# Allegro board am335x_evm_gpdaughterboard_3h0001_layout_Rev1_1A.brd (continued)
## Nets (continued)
VDDSHV1: C1.1 C21.1 C22.1 C23.1 C24.1 C25.1 C30.1 C31.1 C35.1 C36.1 C37.1 C38.1 C80.1 C81.1 R1.2(P2) R2.2(P2) R6.2(P2) R18.2(P2) R19.2(P2) R20.2(P2) R247.2(P2) U1.1(A0) U1.8(VCC) U5.12(VCC#12) U5.34(VCC#34) U5.37(VCC#37) U5.39(VCC#39) U6.31(VCCA#31) U6.42(VCCA#42) U7.7(VCCB#7) U7.18(VCCB#18) U7.31(VCCA#31) U7.42(VCCA#42) U23.5(VCCA) U23.17(VCCB1)
VDDSHV2: C7.1 C77.1 J4.11 R47.2(P2) U23.21(VCCB0)
VDDSHV3: C26.1 C28.1 R3.2(P2) R7.2(P2) U4.1(1DIR) U4.24(2DIR) U4.31(VCCA#31) U4.42(VCCA#42)
VDDSHV5: R4.2(P2) R8.2(P2)
VDDSHV6: C13.1 C14.1 C40.1 C44.1 R5.2(P2) R9.2(P2) U2.1(1DIR) U2.24(2DIR) U2.31(VCCA#31) U2.42(VCCA#42) U10.3(VCCA) U11.3(VCCA)
ACCEL_INT1: U9.11(INT1) U43.L5(IO_B1_L5)
ACCEL_INT2: U9.9(INT2) U43.L6(IO_B1_L6)
AM335X_ECAP0_IN_PWM0_OUT: J3.19 U43.B12(IO_B2_B12)
AM335X_GPMC_A0: J4.2 U43.D9(IO_B2_D9)
AM335X_GPMC_A1: J4.4 U43.D10(IO_B2_D10)
AM335X_GPMC_A2: J4.6 U43.D11(IO_B2_D11)
AM335X_GPMC_A3: J4.8 U43.D12(IO_B2_D12)
AM335X_GPMC_A4: J4.10 U4.41(1A5) U43.D13(IO_B2_D13)
AM335X_GPMC_A5: J4.12 U4.40(1A6) U43.D14(IO_B2_D14)
AM335X_GPMC_A6: J4.16 U4.38(1A7) U43.E6(IO_B2_E6)
AM335X_GPMC_A7: J4.18 U4.37(1A8) U43.E7(IO_B2_E7)
AM335X_GPMC_A8: J4.22 U4.47(1A1) U43.E8(IO_B2_E8)
AM335X_GPMC_A9: J4.24 U4.46(1A2) U43.E9(IO_B2_E9)
AM335X_GPMC_A10: J4.26 U4.44(1A3) U43.E10(IO_B2_E10)
AM335X_GPMC_A11: J4.28 U4.43(1A4) U43.E11(IO_B2_E11)
AM335X_GPMC_AD0: J1.17 U23.6(DAT0A)
AM335X_GPMC_AD1: J1.15 U23.7(DAT1A)
AM335X_GPMC_AD2: J1.13 U23.1(DAT2A)
AM335X_GPMC_AD3: J1.11 U23.3(DAT3A)
AM335X_GPMC_AD4: J1.9 R251.2(P2) R255.2(P2)
AM335X_GPMC_AD5: J1.7 R252.2(P2) R257.2(P2)
AM335X_GPMC_AD6: J1.5 R253.2(P2) R256.2(P2)
AM335X_GPMC_AD7: J1.3 R254.2(P2) R258.2(P2)
AM335X_GPMC_AD8: J5.11 U43.R14(IO_B4_R14)
AM335X_GPMC_AD9: J5.14 U43.R13(IO_B4_R13)
AM335X_GPMC_AD10: J6.4 U43.R12(IO_B4_R12)
AM335X_GPMC_AD11: J6.3 U43.R11(IO_B4_R11)
AM335X_GPMC_AD12: J5.13 U43.R10(IO_B4_R10)
AM335X_GPMC_AD13: J6.6 U43.P13(IO_B4_P13)
AM335X_GPMC_AD14: J6.5 U43.P12(IO_B4_P12)
AM335X_GPMC_AD15: J6.8 U43.P11(IO_B4_P11)
AM335X_GPMC_ADVN_ALE: J2.26 U43.G7(IO_B1_G7)
AM335X_GPMC_BE0N_CLE: J2.28 U43.H1(IO_B1_H1)
AM335X_GPMC_BE1N: J3.2 U43.J1(IO_B1_J1)
AM335X_GPMC_CLK: J2.23 U43.H4(IO_B1_H4)
AM335X_GPMC_CS0N: J2.25 U43.H5(IO_B1_H5)
AM335X_GPMC_CS1N: J1.21 U23.9(CLKA)
AM335X_GPMC_CS2N: J1.19 U23.4(CMDA)
AM335X_GPMC_CS3N: J3.4 U43.J2(IO_B1_J2)
AM335X_GPMC_OEN_REN: J3.6 U43.J3(IO_B1_J3)
AM335X_GPMC_WAIT: J2.19 U43.H2(IO_B1_H2)
AM335X_GPMC_WEN: J3.8 U43.A2(IO_B2_A2)
AM335X_GPMC_WPN: J2.21 U43.H3(IO_B1_H3)
AM335X_I2C0_SCL: J6.14 J20.14 U1.6(SCL) U43.M5(IO_B1_M5)
AM335X_I2C0_SDA: J5.15 J19.15 U1.5(SDA) U43.M6(IO_B1_M6)
AM335X_MCASP0_ACLKR: J4.17 U43.F9(IO_B2_F9)
AM335X_MCASP0_ACLKX: J4.1 U43.E12(IO_B2_E12)
AM335X_MCASP0_AHCLKR: J4.13 U43.F8(IO_B2_F8)
AM335X_MCASP0_AHCLKX: J4.27 U43.F12(IO_B2_F12)
AM335X_MCASP0_AXR0: J4.7 U43.F7(IO_B2_F7)
AM335X_MCASP0_AXR1: J4.23 U43.F11(IO_B2_F11)
AM335X_MCASP0_FSR: J4.21 U43.F10(IO_B2_F10)
AM335X_MCASP0_FSX: J4.5 U43.E13(IO_B2_E13)
AM335X_MDIO_CLK: J3.9 TP79.1
AM335X_MDIO_DATA: J3.7 TP78.1
AM335X_MMC0_CLK: J3.12 U43.A4(IO_B2_A4)
AM335X_MMC0_CMD: J3.14 U43.A5(IO_B2_A5)
AM335X_MMC0_DAT0: J3.16 U43.A6(IO_B2_A6)
AM335X_MMC0_DAT1: J3.22 U43.A8(IO_B2_A8)
AM335X_MMC0_DAT2: J3.24 U43.A9(IO_B2_A9)
AM335X_MMC0_DAT3: J3.26 U43.A10(IO_B2_A10)
AM335X_RMII1_COL: J3.34 U43.A17(IO_B2_A17)
AM335X_RMII1_CRS: J3.36 U43.B1(IO_B2_B1)
AM335X_RMII1_REFCLK: J3.3 U43.B5(IO_B2_B5)
AM335X_RMII1_RXCLK: J1.8 U43.D1(IO_B1_D1)
AM335X_RMII1_RXD0: J3.5 U43.B6(IO_B2_B6)
AM335X_RMII1_RXD1: J1.22 U43.E4(IO_B1_E4)
AM335X_RMII1_RXD2: J1.10 U43.D2(IO_B1_D2)
AM335X_RMII1_RXD3: J1.4 U43.C2(IO_B1_C2)
AM335X_RMII1_RXDV: J1.14 U43.D4(IO_B1_D4)
AM335X_RMII1_RXERR: J3.38 U43.B3(IO_B2_B3)
AM335X_RMII1_TXCLK: J1.6 U43.C3(IO_B1_C3)
AM335X_RMII1_TXD0: J1.20 U43.E3(IO_B1_E3)
AM335X_RMII1_TXD1: J1.18 U43.E2(IO_B1_E2)
AM335X_RMII1_TXD2: J1.12 U43.D3(IO_B1_D3)
AM335X_RMII1_TXD3: J1.16 U43.E1(IO_B1_E1)
AM335X_RMII1_TXEN: J3.40 U43.B4(IO_B2_B4)
AM335X_SPI0_CLK: J3.13 U43.B9(IO_B2_B9)
AM335X_SPI0_CS0: J1.24 U10.5(A1) U43.E5(IO_B1_E5)
AM335X_SPI0_CS1: J3.17 U43.B11(IO_B2_B11)
AM335X_SPI0_D0: J3.15 U43.B10(IO_B2_B10)
AM335X_SPI0_D1: J1.23 U10.4(A2) U43.G6(IO_B1_G6)
AM335X_TSC_CLK: J7.5 U43.T7(IO_B4_T7)
AM335X_TSC_GIO0: J7.1 U43.T5(IO_B4_T5)
AM335X_TSC_GIO1: J7.3 U43.T6(IO_B4_T6)
AM335X_TSC_GIO2: J7.8 U43.T10(IO_B4_T10)
AM335X_TSC_RSV0: J7.7 TP4.1
AM335X_TSC_RSV1_VREF: J7.9 TP5.1
AM335X_UART0_CTSN: J3.21 U43.B13(IO_B2_B13)
AM335X_UART0_RTSN: J3.23 U43.B14(IO_B2_B14)
AM335X_UART0_RXD: J3.25 U43.B15(IO_B2_B15)
AM335X_UART0_TXD: J3.27 U43.B16(IO_B2_B16)
AM335X_UART1_CTSN: J3.29 U11.4(A2) U43.B18(IO_B2_B18)
AM335X_UART1_RTSN: J3.31 U11.5(A1) U43.C4(IO_B2_C4)
AM335X_UART1_RXD: J3.33 U43.C5(IO_B2_C5)
AM335X_UART1_TXD: J3.35 U43.C6(IO_B2_C6)
AM335X_WAKEUP: J3.18 R126.1(P1) U42.6(1Y) U43.A7(IO_B2_A7)
AM335X_XDMA_EVENT_INTR0: J3.28 U43.A14(IO_B2_A14)
AM335X_XDMA_EVENT_INTR1: J3.32 R158.2(P2) U43.A15(IO_B2_A15)
AUD_BCLK: U43.E15(IO_B3_E15) U51.38(BCLK)
AUD_DIN: U43.F15(IO_B3_F15) U51.40(DIN)
AUD_DOUT: U43.F14(IO_B3_F14) U51.41(DOUT)
AUD_FSX: U43.F13(IO_B3_F13) U51.39(WCLK)
AUD_HPLOUT: C198.1 U51.18(HPLOUT)
AUD_HPLOUT_JCK: C198.2 J26.2(P2)
AUD_HPOUTCABLEDET: U43.K14(IO_B3_K14)
AUD_HPROUT: C197.1 U51.23(HPROUT)
AUD_HPROUT_JCK: C197.2 J26.3(P3)
AUD_LINEINCABLEDET: U43.K15(IO_B3_K15)
AUD_MCLK: R231.1(P1) R233.1(P1) U51.37(MCLK)
AUD_MCLK_CPLD: R233.2(P2) U43.E16(IO_B3_E16)
AUD_RESETN: R232.1(P1) U51.33(RESETN)
AUD_VOLUMEDWN: R236.1(P1) SW10.1 SW10.2 U43.R6(IO_B4_R6)
AUD_VOLUMEUP: R235.1(P1) SW9.1 SW9.2 U43.R5(IO_B4_R5)
AUDIO_BUZZER_TRIG: Q9.G(GATE) R124.2(P2) U43.L4(IO_B1_L4)
BUZZER_N: Q9.D(DRAIN) SPKR1.2(NEG-)
BUZZER_P: R120.1 SPKR1.1(POS+)
CAN0_H: J11.7 U16.7(CANH) U17.1
CAN0_L: J11.2 U16.6(CANL) U17.2
CAN0_RXD: C57.1 R43.1 U43.J15(IO_B3_J15)
CAN0_RXDF: R43.2 U16.2(RXD)
CAN0_TXD: R44.1 U43.J16(IO_B3_J16)
CAN0_TXDF: C58.1 R44.2 U16.3(TXD)
CPLD_CFG0: R151.2(P2) SW8.1 U43.P10(IO_B4_P10)
CPLD_CFG1: R150.2(P2) SW8.2 U43.R7(IO_B4_R7)
CPLD_CFG2: R149.2(P2) SW8.3 U43.R8(IO_B4_R8)
CPLD_CFG3: R148.2(P2) SW8.4 U43.R9(IO_B4_R9)
CPLD_CLK12MHZ: R230.1(P1) U43.J6(GCLK0P)
CPLD_CLK25MHZ: R157.1(P1) U43.K6(GCLK1P)
CPLD_CLKSA: R158.1(P1) U43.K13(GCLK2P)
CPLD_CLRN: R156.1(P1) U43.N10(DEV_CLRN)
CPLD_DEVOE: TP32.1 U43.N9(DEV_OE)
CPLD_GCLK3: TP33.1 U43.J13(GCLK3P)
CPLD_TCK: J22.1 R159.2(P2) U43.R4(TCK)
CPLD_TDI: J22.9 R153.1(P1) U43.M7(TDI)
CPLD_TDO: J22.3 R154.1(P1) U43.N6(TDO)
CPLD_TMS: J22.5 R155.1(P1) U43.P5(TMS)
EXP3_P9: J4.9 TP3.1
EXP_PB_POWERON: J2.12 TP1.1
F_TSC_CLK: J21.5 U43.F17(IO_B3_F17)
F_TSC_GIO0: J21.1 U43.F18(IO_B3_F18)
F_TSC_GIO1: J21.3 U43.G12(IO_B3_G12)
F_TSC_GIO2: J21.8 U43.G13(IO_B3_G13)
F_TSC_RSV0: J21.7 U43.F16(IO_B3_F16)
GP_I2C_SCL: R23.1(P1) U9.4(SCL/SPC) U10.8(B1) U11.8(B1) U12.3(SMBCLK) U13.2(SCL) U39.14(SCL) U40.14(SCL) U51.1(SCL)
GP_I2C_SDA: R24.1(P1) U9.6(SDA/SDI/SDO) U10.1(B2) U11.1(B2) U12.4(SMBDATA) U13.1(SDA) U39.15(SDA) U40.15(SDA) U51.2(SDA)
GPMC_AD0: U6.47(1A1) U7.47(1A1) U23.14(DAT0B1) U43.G3(IO_B1_G3)
GPMC_AD1: U6.46(1A2) U7.46(1A2) U23.15(DAT1B1) U43.G2(IO_B1_G2)
GPMC_AD2: U6.44(1A3) U7.44(1A3) U23.8(DAT2B1) U43.G1(IO_B1_G1)
GPMC_AD3: U6.43(1A4) U7.43(1A4) U23.10(DAT3B1) U43.F6(IO_B1_F6)
GPMC_AD4: R255.1(P1) U6.41(1A5) U7.41(1A5) U43.F5(IO_B1_F5)
GPMC_AD5: R257.1(P1) U6.40(1A6) U7.40(1A6) U43.F4(IO_B1_F4)
GPMC_AD6: R256.1(P1) U6.38(1A7) U7.38(1A7) U43.F3(IO_B1_F3)
GPMC_AD7: R258.1(P1) U6.37(1A8) U7.37(1A8) U43.F2(IO_B1_F2)
GPMC_AD8: U6.36(2A1) U7.36(2A1)
GPMC_AD9: U6.35(2A2) U7.35(2A2)
GPMC_AD10: U6.33(2A3) U7.33(2A3)
GPMC_AD11: U6.32(2A4) U7.32(2A4)
GPMC_AD12: U6.30(2A5) U7.30(2A5)
GPMC_AD13: U6.29(2A6) U7.29(2A6)
GPMC_AD14: U6.27(2A7) U7.27(2A7)
GPMC_AD15: U6.26(2A8) U7.26(2A8)
GPMC_CS1N: U23.13(CLKB1) U43.G5(IO_B1_G5)
GPMC_CS2N: U23.12(CMDB1) U43.G4(IO_B1_G4)
HAPT_N: Q10.D(DRAIN) U41.2(N-)
HAPT_P: C129.1 R125.1(P1) U41.1(P+)
HAPTICS_TRIG: Q10.G(GATE) R128.2(P2) U43.L15(IO_B3_L15)
IDMEM_WP: R1.1(P1) U1.7(WP)
IOEXPAND0_D0: J18.2 U39.4(P0)
IOEXPAND0_D1: J18.4 U39.5(P1)
IOEXPAND0_D2: J18.6 U39.6(P2)
IOEXPAND0_D3: J18.8 U39.7(P3)
IOEXPAND0_D4: J18.12 Q1.G(GATE) R112.2(P2) U39.9(P4)
IOEXPAND0_D5: J18.14 Q2.G(GATE) R114.2(P2) U39.10(P5)
IOEXPAND0_D6: J18.16 Q3.G(GATE) R115.2(P2) U39.11(P6)
IOEXPAND0_D7: J18.18 Q4.G(GATE) R116.2(P2) U39.12(P7)
IOEXPAND0_INTN: R100.1(P1) U39.13(I\N\T\) U43.P4(IO_B1_P4)
IOEXPAND1_D0: J18.1 U40.4(P0)
IOEXPAND1_D1: J18.3 U40.5(P1)
IOEXPAND1_D2: J18.5 U40.6(P2)
IOEXPAND1_D3: J18.7 U40.7(P3)
IOEXPAND1_D4: J18.11 Q5.G(GATE) R113.2(P2) U40.9(P4)
IOEXPAND1_D5: J18.13 Q6.G(GATE) R117.2(P2) U40.10(P5)
IOEXPAND1_D6: J18.15 Q7.G(GATE) R118.2(P2) U40.11(P6)
IOEXPAND1_D7: J18.17 Q8.G(GATE) R119.2(P2) U40.12(P7)
IOEXPAND1_INTN: R101.1(P1) U40.13(I\N\T\) U43.R3(IO_B1_R3)
KEYPAD_PWRA: SW1.1 SW1.2 SW2.1 SW2.2 SW3.1 SW3.2 U43.U3(IO_B4_U3)
KEYPAD_PWRB: SW4.1 SW4.2 SW5.1 SW5.2 SW6.2 U43.U4(IO_B4_U4)
KEYPAD_SCN0: C125.1 R121.2(P2) SW1.3 SW1.4 SW4.3 SW4.4 U43.T8(IO_B4_T8)
KEYPAD_SCN1: C126.1 R122.2(P2) SW2.3 SW2.4 SW5.3 SW5.4 U43.T9(IO_B4_T9)
KEYPAD_SCN2: C127.1 R123.2(P2) SW3.3 SW3.4 SW6.4 U43.U1(IO_B4_U1)
LCD_DATA0: J5.4 U2.47(1A1) U43.U10(IO_B4_U10)
LCD_DATA1: J5.3 U2.46(1A2) U43.U11(IO_B4_U11)
LCD_DATA2: J5.6 U2.44(1A3) U43.U12(IO_B4_U12)
LCD_DATA3: J5.5 U2.43(1A4) U43.U13(IO_B4_U13)
LCD_DATA4: J5.8 U2.41(1A5) U43.U14(IO_B4_U14)
LCD_DATA5: J5.7 U2.40(1A6) U43.U15(IO_B4_U15)
LCD_DATA6: J6.15 U2.38(1A7) U43.U16(IO_B4_U16)
LCD_DATA7: J6.9 U2.37(1A8) U43.U18(IO_B4_U18)
LCD_DATA8: J6.11 U2.36(2A1) U43.T11(IO_B4_T11)
LCD_DATA9: J6.13 U2.35(2A2) U43.T12(IO_B4_T12)
LCD_DATA10: J5.10 U2.33(2A3) U43.T13(IO_B4_T13)
LCD_DATA11: J5.16 U2.32(2A4) U43.T14(IO_B4_T14)
LCD_DATA12: J5.9 U2.30(2A5) U43.T15(IO_B4_T15)
LCD_DATA13: J6.10 U2.29(2A6) U43.V14(IO_B4_V14)
LCD_DATA14: J5.12 U2.27(2A7) U43.V15(IO_B4_V15)
LCD_DATA15: J6.7 U2.26(2A8) U43.V17(IO_B4_V17)
LCD_DEN: J6.17 U43.V10(IO_B4_V10)
LCD_HSYNC: J6.18 U43.V12(IO_B4_V12)
LCD_PCLK: J6.16 U43.V11(IO_B4_V11)
LCD_VSYNC: J5.17 U43.V13(IO_B4_V13)
LCDA_PIN18: J5.18 R13.2(P2)
LCDBD_D0: J19.4 U43.R17(IO_B3_R17)
LCDBD_D1: J19.3 U43.R16(IO_B3_R16)
LCDBD_D2: J19.6 U43.P17(IO_B3_P17)
LCDBD_D3: J19.5 U43.P16(IO_B3_P16)
LCDBD_D4: J19.8 U43.N18(IO_B3_N18)
LCDBD_D5: J19.7 U43.N17(IO_B3_N17)
LCDBD_D6: J20.15 U43.N16(IO_B3_N16)
LCDBD_D7: J20.9 U43.M18(IO_B3_M18)
LCDBD_D8: J20.11 U43.M17(IO_B3_M17)
LCDBD_D9: J20.13 U43.M16(IO_B3_M16)
LCDBD_D10: J19.10 U43.L18(IO_B3_L18)
LCDBD_D11: J19.16 U43.L17(IO_B3_L17)
LCDBD_D12: J19.9 U43.L16(IO_B3_L16)
LCDBD_D13: J20.10 U43.K18(IO_B3_K18)
LCDBD_D14: J19.12 U43.K17(IO_B3_K17)
LCDBD_D15: J20.7 U43.K16(IO_B3_K16)
LCDBD_D16: J20.8 U43.R15(IO_B3_R15)
LCDBD_D17: J20.5 U43.P15(IO_B3_P15)
LCDBD_D18: J20.6 U43.P14(IO_B3_P14)
LCDBD_D19: J19.13 U43.N15(IO_B3_N15)
LCDBD_D20: J20.3 U43.N14(IO_B3_N14)
LCDBD_D21: J20.4 U43.N13(IO_B3_N13)
LCDBD_D22: J19.14 U43.M15(IO_B3_M15)
LCDBD_D23: J19.11 U43.M14(IO_B3_M14)
LCDBD_DEN: J20.17 U43.T17(IO_B3_T17)
LCDBD_HSYNC: J20.18 U43.R18(IO_B3_R18)
LCDBD_PCLK: J20.16 U43.P18(IO_B3_P18)
LCDBD_VSYNC: J19.17 U43.T16(IO_B3_T16)
LCDBDA_PIN18: J19.18 R146.2(P2)
LED0_TRIG: Q11.G(GATE) R137.2(P2) U43.N7(IO_B4_N7)
LED1_TRIG: Q12.G(GATE) R139.2(P2) U43.N8(IO_B4_N8)
LED2_TRIG: Q13.G(GATE) R140.2(P2) U43.N11(IO_B4_N11)
LED3_TRIG: Q14.G(GATE) R141.2(P2) U43.N12(IO_B4_N12)
LED4_TRIG: Q15.G(GATE) R138.2(P2) U43.P6(IO_B4_P6)
LED5_TRIG: Q16.G(GATE) R142.2(P2) U43.P7(IO_B4_P7)
LED6_TRIG: Q17.G(GATE) R143.2(P2) U43.P8(IO_B4_P8)
LED7_TRIG: Q18.G(GATE) R144.2(P2) U43.P9(IO_B4_P9)
MMC1_MUXCTRL: R247.1(P1) U23.24(SEL) U43.K5(IO_B1_K5)
MON_AIN0: J8.1 R34.1(P1)
MON_AIN1: J8.3 R35.1(P1)
MON_AIN2: J8.7 R38.1(P1)
MON_AIN3: J8.9 R40.1(P1)
MON_AIN4: J8.2 R36.2(P2)
MON_AIN5: J8.4 R37.2(P2)
MON_AIN6: J8.8 R39.2(P2)
MON_AIN7: J8.10 R41.2(P2)
MUXCTRL_I2C1: R26.2(P2) U10.6(OE) U43.E17(IO_B3_E17)
MUXCTRL_I2C2: R30.2(P2) U11.6(OE) U43.E18(IO_B3_E18)
NAND_ADVN_ALE: U5.17(ALE) U43.D17(IO_B3_D17)
NAND_BE0N_CLE: U5.16(CLE) U43.D16(IO_B3_D16)
NAND_CSN: R20.1(P1) U5.9(\\C\E\) U7.25(2O\E\) U7.48(1O\E\) U43.D15(IO_B3_D15)
NAND_D0: U5.29(I/O0) U7.2(1B1)
NAND_D1: U5.30(I/O1) U7.3(1B2)
NAND_D2: U5.31(I/O2) U7.5(1B3)
NAND_D3: U5.32(I/O3) U7.6(1B4)
NAND_D4: U5.41(I/O4) U7.8(1B5)
NAND_D5: U5.42(I/O5) U7.9(1B6)
NAND_D6: U5.43(I/O6) U7.11(1B7)
NAND_D7: U5.44(I/O7) U7.12(1B8)
NAND_D8: U5.26(NC_IO8) U7.13(2B1)
NAND_D9: U5.27(NC_IO9) U7.14(2B2)
NAND_D10: U5.28(NC_IO10) U7.16(2B3)
NAND_D11: U5.33(NC_IO11) U7.17(2B4)
NAND_D12: U5.40(NC_IO12) U7.19(2B5)
NAND_D13: U5.45(NC_IO13) U7.20(2B6)
NAND_D14: U5.46(NC_IO14) U7.22(2B7)
NAND_D15: U5.47(NC_IO15) U7.23(2B8)
NAND_OEN: U5.8(\\R\E) U7.1(1DIR) U7.24(2DIR) U43.C17(IO_B3_C17)
NAND_WAIT: R18.1(P1) U5.7(R/\B\) U43.C16(IO_B3_C16)
NAND_WEN: U5.18(\\W\E) U43.D18(IO_B3_D18)
NAND_WPN: R19.1(P1) U5.19(\\W\P) U43.E14(IO_B3_E14)
NC0: U9.2(NC0)
NC1: U9.3(NC1)
NOR_A0: R250.1(P1) U2.2(1B1)
NOR_A1: U2.3(1B2) U3.E2(A0)
NOR_A2: U2.5(1B3) U3.D2(A1)
NOR_A3: U2.6(1B4) U3.C2(A2)
NOR_A4: U2.8(1B5) U3.A2(A3)
NOR_A5: U2.9(1B6) U3.B2(A4)
NOR_A6: U2.11(1B7) U3.D3(A5)
NOR_A7: U2.12(1B8) U3.C3(A6)
NOR_A8: U3.A3(A7) U4.2(1B1)
NOR_A9: U3.B6(A8) U4.3(1B2)
NOR_A10: U3.A6(A9) U4.5(1B3)
NOR_A11: U3.C6(A10) U4.6(1B4)
NOR_A12: U2.13(2B1) U3.D6(A11)
NOR_A13: U2.14(2B2) U3.B7(A12)
NOR_A14: U2.16(2B3) U3.A7(A13)
NOR_A15: U2.17(2B4) U3.C7(A14)
NOR_A16: U2.19(2B5) U3.D7(A15)
NOR_A17: U2.20(2B6) U3.E7(A16)
NOR_A18: U2.22(2B7) U3.B3(A17)
NOR_A19: U2.23(2B8) U3.C4(A18)
NOR_A20: U3.D5(A19) U4.8(1B5)
NOR_A21: U3.D4(A20) U4.9(1B6)
NOR_A22: U3.C5(A21) U4.11(1B7)
NOR_A23: U3.B8(A22) U4.12(1B8)
NOR_BYTEN: R14.1(P1) R259.2(P2) U3.F7(B\Y\T\E\)
NOR_CEN: R15.1(P1) U2.25(2O\E\) U2.48(1O\E\) U3.F2(E\) U4.25(2O\E\) U4.48(1O\E\) U6.25(2O\E\) U6.48(1O\E\) U43.C8(IO_B2_C8)
NOR_D0: U3.E3(DQ0) U6.2(1B1)
NOR_D1: U3.H3(DQ1) U6.3(1B2)
NOR_D2: U3.E4(DQ2) U6.5(1B3)
NOR_D3: U3.H4(DQ3) U6.6(1B4)
NOR_D4: U3.H5(DQ4) U6.8(1B5)
NOR_D5: U3.E5(DQ5) U6.9(1B6)
NOR_D6: U3.H6(DQ6) U6.11(1B7)
NOR_D7: U3.E6(DQ7) U6.12(1B8)
NOR_D8: U3.F3(DQ8) U6.13(2B1)
NOR_D9: U3.G3(DQ9) U6.14(2B2)
NOR_D10: U3.F4(DQ10) U6.16(2B3)
NOR_D11: U3.G4(DQ11) U6.17(2B4)
NOR_D12: U3.F5(DQ12) U6.19(2B5)
NOR_D13: U3.G6(DQ13) U6.20(2B6)
NOR_D14: U3.F6(DQ14) U6.22(2B7)
NOR_D15: R249.1(P1) U6.23(2B8)
NOR_D15A0: R249.2(P2) R250.2(P2) U3.G7(DQ15)
NOR_OEN: U3.G2(G\) U6.1(1DIR) U6.24(2DIR) U43.C9(IO_B2_C9)
NOR_READY: U3.A4(RB\) U43.C14(IO_B2_C14)
NOR_RESETN: U3.B5(R\P\) U43.C13(IO_B2_C13)
NOR_WEN: U3.A5(W\) U43.C7(IO_B2_C7)
PMIC_PWR_EN: J1.25 R11.2(P2) R238.2(P2) R242.2(P2)
RS232_1_CTS: J10.8 U15.8(RIN2)
RS232_1_RTS: J10.7 U15.7(DOUT2)
RS232_1_RXD: J10.2 U15.13(RIN1)
RS232_1_TXD: J10.3 U15.14(DOUT1)
RS232_2_CTS: J12.8 U19.8(RIN2)
RS232_2_RTS: J12.7 U19.7(DOUT2)
RS232_2_RXD: J12.2 U19.13(RIN1)
RS232_2_TXD: J12.3 U19.14(DOUT1)
RS232_3_CTS: J14.8 U22.8(RIN2)
RS232_3_RTS: J14.7 U22.7(DOUT2)
RS232_3_RXD: J14.2 U22.13(RIN1)
RS232_3_TXD: J14.3 U22.14(DOUT1)
SDMMC1_CD: J15.15(CD) R57.1(P1) U27.3(IO1) U43.V9(IO_B4_V9)
SDMMC1_CLK: J15.5(#5_MMC+/MMCM/RSMMC/MMC/SD) J15.20(#5_MINISD) U23.19(CLKB0) U25.1(IO1)
SDMMC1_CMD: J15.2(#2_MMC+/MMCM/RSMMC/MMC/SD) J15.17(#2_MINISD) R49.1(P1) U23.20(CMDB0) U25.7(IO5)
SDMMC1_DAT0: J15.7(#7_MMC+/MMCM/RSMMC/MMC/SD) J15.22(#7_MINISD) R50.1(P1) U23.18(DAT0B0) U25.2(IO2)
SDMMC1_DAT1: J15.8(#8_MMC+/MMCM/SD) J15.23(#8_MINISD) R51.1(P1) U23.16(DAT1B0) U25.3(IO3)
SDMMC1_DAT2: J15.9(#9_MMC+/MMCM/SD) J15.24(#9_MINISD) R52.1(P1) U23.23(DAT2B0) U25.6(IO4)
SDMMC1_DAT3: J15.1(#1_MMC+/MMCM/RSMMC/MMC/SD) J15.16(#1_MINISD) R48.1(P1) U23.22(DAT3B0) U25.8(IO6)
SDMMC1_DAT4: J15.10(#10_MMC+/MMCM) R53.1(P1) R251.1(P1) U26.1(IO1)
SDMMC1_DAT5: J15.11(#11_MMC+/MMCM) R54.1(P1) R252.1(P1) U26.2(IO2)
SDMMC1_DAT6: J15.12(#12_MMC+/MMCM) R55.1(P1) R253.1(P1) U26.7(IO5)
SDMMC1_DAT7: J15.13(#13_MMC+/MMCM) R56.1(P1) R254.1(P1) U26.8(IO6)
SDMMC1_WP: J15.14(SD_WP) U27.5(IO2) U43.T4(IO_B4_T4)
SMA_AIN1: J9.1(IN) R42.1(P1)
SPIMEM_CLK: U8.6(CLK) U43.K1(IO_B1_K1)
SPIMEM_CS: U8.1(C\S\) U43.K4(IO_B1_K4)
SPIMEM_DI: U8.5(DI) U43.K2(IO_B1_K2)
SPIMEM_DO: U8.2(DO) U43.K3(IO_B1_K3)
SPIMEM_HOLDN: R22.1(P1) U8.7(H\O\L\D\) U43.L1(IO_B1_L1)
SPIMEM_WPN: R21.1(P1) U8.3(W\P\) U43.L2(IO_B1_L2)
SYS_RESETN: J1.26 R10.2(P2) R156.2(P2) R232.2(P2) U39.3(R\E\S\E\T\) U40.3(R\E\S\E\T\)
SYS_WARMRESETN: J2.11 TP2.1
TEMP_ALERT: R31.1(P1) U13.3(ALERT) U43.U5(IO_B4_U5)
TSC_AIN0: J7.14 J21.14 R34.2(P2)
TSC_AIN1: J7.16 J21.16 R35.2(P2) R42.2(P2)
TSC_AIN2: J7.18 J21.18 R38.2(P2)
TSC_AIN3: J7.20 J21.20 R40.2(P2)
TSC_AIN4: J7.13 J21.13 R36.1(P1)
TSC_AIN5: J7.15 J21.15 R37.1(P1)
TSC_AIN6: J7.17 J21.17 R39.1(P1)
TSC_AIN7: J7.19 J21.19 R41.1(P1)
TSC_I2CSCL: J7.4 J21.4
TSC_I2CSDA: J7.6 J21.6
TSC_RSV1_VREF: J21.9 TP13.1
UART1_CTS: U15.9(ROUT2) U43.G17(IO_B3_G17)
UART1_RTS: U15.10(DIN2) U43.G15(IO_B3_G15)
UART1_RXD: U15.12(ROUT1) U43.G16(IO_B3_G16)
UART1_TXD: U15.11(DIN1) U43.G14(IO_B3_G14)
UART2_CTS: U19.9(ROUT2) U43.H15(IO_B3_H15)
UART2_RTS: U19.10(DIN2) U43.H13(IO_B3_H13)
UART2_RXD: U19.12(ROUT1) U43.H14(IO_B3_H14)
UART2_TXD: U19.11(DIN1) U43.G18(IO_B3_G18)
UART3_CTS: U22.9(ROUT2) U43.J14(IO_B3_J14)
UART3_RTS: U22.10(DIN2) U43.H17(IO_B3_H17)
UART3_RXD: U22.12(ROUT1) U43.H18(IO_B3_H18)
UART3_TXD: U22.11(DIN1) U43.H16(IO_B3_H16)
VCAN0: C52.1 C54.1 J11.9 U14.7(VOUT+) U16.8(VCC2)
VCPLD_INT: C138.1 C139.1 C140.1 C141.1 C142.1 C143.1 C144.1 C145.1 C146.1 R160.1(P1) U43.G11(VCCINT#G11) U43.H12(VCCINT#H12) U43.J9(VCCINT#J9) U43.J11(VCCINT#J11) U43.K8(VCCINT#K8) U43.K10(VCCINT#K10) U43.L7(VCCINT#L7) U43.M8(VCCINT#M8)
VCPLD_VIO1: C137.1 C157.1 C158.1 C159.1 C160.1 C161.1 J22.4 R153.2(P2) R154.2(P2) R155.2(P2) R161.1(P1) R162.1(P1) U43.C1(VCCIO1#C1) U43.J7(VCCIO1#J7) U43.K7(VCCIO1#K7) U43.T1(VCCIO1#T1)
VCPLD_VIO2: C147.1 C148.1 C149.1 C150.1 C151.1 R163.1(P1) R164.1(P1) U43.A3(VCCIO2#A3) U43.A16(VCCIO2#A16) U43.G9(VCCIO2#G9) U43.G10(VCCIO2#G10)
VCPLD_VIO3: C152.1 C153.1 C154.1 C155.1 C156.1 R165.1(P1) R166.1(P1) U43.C18(VCCIO3#C18) U43.J12(VCCIO3#J12) U43.K12(VCCIO3#K12) U43.T18(VCCIO3#T18)
VCPLD_VIO4: C162.1 C163.1 C164.1 C165.1 C166.1 R167.1(P1) R168.1(P1) U43.M9(VCCIO4#M9) U43.M10(VCCIO4#M10) U43.V3(VCCIO4#V3) U43.V16(VCCIO4#V16)
VEXPD: C6.1 C11.1 C134.1 C227.1 C230.1 J4.19 J6.1 J20.1 R104.2(P2) R105.2(P2) R106.2(P2) R107.2(P2) R108.2(P2) R109.2(P2) R110.2(P2) R111.2(P2) R120.2 R125.2(P2) R129.2(P2) R130.2(P2) R131.2(P2) R132.2(P2) R133.2(P2) R134.2(P2) R135.2(P2) R136.2(P2) U52.2(IN) U53.2(IN)
VGP_1_8D: C228.1 C229.1 R241.2(P2) R243.2(P2) U53.4(OUT)
VGP_1_8DEN: R242.1(P1) U53.1(EN)
VGP_1_8DFB: C228.2 R243.1(P1) R244.2(P2) U53.5(FB)
VGP_3_3D: C225.1 C226.1 R237.2(P2) R239.2(P2) U52.4(OUT)
VGP_3_3DEN: R238.1(P1) U52.1(EN)
VGP_3_3DFB: C225.2 R239.1(P1) R240.2(P2) U52.5(FB)
VSDMMC1: C78.1 C79.1 J15.4(#4_MMC+/MMCM/RSMMC/MMC/SD) J15.19(#4_MINISD) R47.1(P1) R48.2(P2) R49.2(P2) R50.2(P2) R51.2(P2) R52.2(P2) R53.2(P2) R54.2(P2) R55.2(P2) R56.2(P2) U25.10(VCC) U26.10(VCC)
WAKEUP_SW: C130.1 R127.1(P1) SW7.1 SW7.2 U42.1(1A)
N16791163: C53.1 U15.2(V+)
N16791168: C56.1 U15.6(V-)
N16791228: C55.2 U15.5(C2-)
N16791231: C55.1 U15.4(C2+)
N16791234: C50.2 U15.3(C1-)
N16791237: C50.1 U15.1(C1+)
N16791926: C63.1 U19.2(V+)
N16791930: C68.1 U19.6(V-)
N16791942: C64.2 U19.5(C2-)
N16791944: C64.1 U19.4(C2+)
N16791946: C62.2 U19.3(C1-)
N16791948: C62.1 U19.1(C1+)
N16792432: C74.1 U22.2(V+)
N16792436: C76.1 U22.6(V-)
N16792448: C75.2 U22.5(C2-)
N16792450: C75.1 U22.4(C2+)
N16792452: C73.2 U22.3(C1-)
N16792454: C73.1 U22.1(C1+)
N16816822: R16.1(P1) R17.2(P2) U3.B4(VPP/W\P\)
N16828302: R103.2(P2) U39.2(ADDR)
N16828557: R102.1(P1) U40.2(ADDR)
N16829115: R27.2(P2) U9.7(SDO/SA0)
N16829117: R25.1(P1) U9.8(CS)
N16843552: R33.2(P2) U13.6(A1)
N16843557: R32.2(P2) U13.7(A0)
N16875858: J6.12 R12.1(P1)
N16973002: J20.12 R145.1(P1)
N16980972: D9.1(CATHODE) Q11.D(DRAIN)
N16980976: D9.2(ANODE) R129.1(P1)
N16981022: D10.1(CATHODE) Q12.D(DRAIN)
N16981031: D10.2(ANODE) R130.1(P1)
N16981067: D11.2(ANODE) R131.1(P1)
N16981069: D11.1(CATHODE) Q13.D(DRAIN)
N16981098: D12.1(CATHODE) Q14.D(DRAIN)
N16981109: D12.2(ANODE) R132.1(P1)
N16982295: D13.1(CATHODE) Q15.D(DRAIN)
N16982308: D13.2(ANODE) R133.1(P1)
N16982335: D14.1(CATHODE) Q16.D(DRAIN)
N16982342: D14.2(ANODE) R134.1(P1)
N16982376: D15.1(CATHODE) Q17.D(DRAIN)
N16982380: D15.2(ANODE) R135.1(P1)
N16982414: D16.1(CATHODE) Q18.D(DRAIN)
N16982428: D16.2(ANODE) R136.1(P1)
N17077837: C209.1 U51.3(LINE1LP)
N17077840: C209.2 J27.2(P2)
N17077863: C210.1 U51.4(LINE1LM)
N17077921: C211.1 U51.5(LINE1RP)
N17077923: C211.2 J27.3(P3)
N17077933: C212.1 U51.6(LINE1RM)
N17102954: C199.1 U51.30(LEFT_LOM)
N17102959: C200.1 U51.29(LEFT_LOP)
N17102964: C201.1 U51.32(RIGHT_ROM)
N17102969: C202.1 U51.31(RIGHT_ROP)
N17102974: C221.1 U51.10(LINE2RM)
N17103265: C222.1 U51.9(LINE2RP)
N17103270: C223.1 U51.28(MONO_LOM)
N17103275: C224.1 U51.27(MONO_LOP)
N17104420: C207.1 U51.14(MIC3R)
N17104425: C206.1 U51.11(MIC3L)
N17104572: C205.1 U51.7(LINE2LP)
N17104759: C208.1 U51.8(LINE2LM)
N17104819: R229.2(P2) Y5.1(OEN)
N17104913: R230.2(P2) R231.2(P2) Y5.3(CLK)
N17284396: D1.1(CATHODE) Q1.D(DRAIN)
N17284409: D1.2(ANODE) R104.1(P1)
N17284436: D2.1(CATHODE) Q2.D(DRAIN)
N17284443: D2.2(ANODE) R105.1(P1)
N17284477: D3.1(CATHODE) Q3.D(DRAIN)
N17284481: D3.2(ANODE) R106.1(P1)
N17284515: D4.1(CATHODE) Q4.D(DRAIN)
N17284529: D4.2(ANODE) R107.1(P1)
N17284999: D5.1(CATHODE) Q5.D(DRAIN)
N17285012: D5.2(ANODE) R108.1(P1)
N17285039: D6.1(CATHODE) Q6.D(DRAIN)
N17285046: D6.2(ANODE) R109.1(P1)
N17285080: D7.1(CATHODE) Q7.D(DRAIN)
N17285084: D7.2(ANODE) R110.1(P1)
N17285118: D8.1(CATHODE) Q8.D(DRAIN)
N17285132: D8.2(ANODE) R111.1(P1)
N17523832: TP80.1 U43.B7(IO_B2_B7)
N17523835: TP81.1 U43.B8(IO_B2_B8)
N17543166: R157.2(P2) Y2.3(CLK)
N17543396: R152.2(P2) Y2.1(OE)
N17609291: TP15.1 U43.A11(IO_B2_A11)
N17609340: TP20.1 U43.A12(IO_B2_A12)
N17609367: TP22.1 U43.A13(IO_B2_A13)
N17609868: TP16.1 U43.C15(IO_B2_C15)
N17609870: TP17.1 U43.C10(IO_B2_C10)
N17609904: TP18.1 U43.C11(IO_B2_C11)
N17609906: TP19.1 U43.C12(IO_B2_C12)
N17609940: TP21.1 U43.D5(IO_B2_D5)
N17609942: TP23.1 U43.D6(IO_B2_D6)
N17609976: TP24.1 U43.D7(IO_B2_D7)
N17609978: TP25.1 U43.D8(IO_B2_D8)
N18557669: TP54.1 U43.V7(IO_B4_V7)
N18557671: TP50.1 U43.V2(IO_B4_V2)
N18557677: TP51.1 U43.V4(IO_B4_V4)
N18557679: TP52.1 U43.V5(IO_B4_V5)
N18557681: TP53.1 U43.V6(IO_B4_V6)
N18557766: TP55.1 U43.V8(IO_B4_V8)
N18557786: TP48.1 U43.U8(IO_B4_U8)
N18557788: TP49.1 U43.U9(IO_B4_U9)
N18559563: TP74.1 U43.R1(IO_B1_R1)
N18559577: TP68.1 U43.N1(IO_B1_N1)
N18559591: TP72.1 U43.P1(IO_B1_P1)
N18559605: TP65.1 U43.M1(IO_B1_M1)
N18559619: TP75.1 U43.R2(IO_B1_R2)
N18559633: TP73.1 U43.P2(IO_B1_P2)
N18559722: TP69.1 U43.N2(IO_B1_N2)
N18559724: TP70.1 U43.N3(IO_B1_N3)
N18559756: TP66.1 U43.M2(IO_B1_M2)
N18559758: TP67.1 U43.M3(IO_B1_M3)
N18559789: TP64.1 U43.L3(IO_B1_L3)
N18559809: TP76.1 U43.T2(IO_B1_T2)
N18559823: TP34.1 U43.P3(IO_B1_P3)
N18560303: TP44.1 U43.J17(IO_B3_J17)
N18560305: TP45.1 U43.J18(IO_B3_J18)
N18561900: TP57.1 U43.J5(IO_B1_J5)
N18561902: TP56.1 U43.J4(IO_B1_J4)
N18561972: TP77.1 U43.M4(IO_B1_M4)
N18561992: TP71.1 U43.N5(IO_B1_N5)
N18561994: TP43.1 U43.N4(IO_B1_N4)
N18562015: TP14.1 U43.T3(IO_B1_T3)
N18562459: TP47.1 U43.U7(IO_B4_U7)
N18562461: TP46.1 U43.U6(IO_B4_U6)
N18562540: TP42.1 U43.L14(IO_B3_L14)
N18562542: TP27.1 U43.L13(IO_B3_L13)
N18562576: TP28.1 U43.M12(IO_B3_M12)
N18562578: TP29.1 U43.M13(IO_B3_M13)
N19691140: TP31.1 U43.H6(IO_B1_H6)
N19778977: TP35.1 U43.F1(IO_B1_F1)

Pads without a net: J2 1 2 3 4 5 6 9 10 13 14 15 16 17 18 20 22 24 27; J10 1 4 6 9; J11 1 4 8; J12 1 4 6 9; J14 1 4 6 9; J15 25 26; J18 19 20; J22 6 7 8; J26 10; J27 10; SW6 1 3; U3 A1 A8 B1 C1 C8 D1 E1 F8 G1 G8 H1 H8; U4 13 14 16 17 19 20 22 23 26 27 29 30 32 33 35 36; U5 1 2 3 4 5 6 10 11 14 15 20 21 22 23 24 35 38; U14 10; U25 4 9; U26 3 4 6 9; U27 2; U42 4; U51 12 13 19 22 34 35 47 48

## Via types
v1: diameter 0.508, hole 0.254, TOP to BOTTOM, 1264 vias
v2: diameter 0.483, hole 0.254, TOP to BOTTOM, 333 vias

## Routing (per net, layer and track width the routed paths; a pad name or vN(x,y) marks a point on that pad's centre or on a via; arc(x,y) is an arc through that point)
AGND_AUD: length 30.8
  TOP w0.279: U51.20 62.66,152.07 v1(62.39,151.8) 62.16,152.04 U51.21 ; U51.15 65.16,152.08 v1(65.44,151.8) ; v1(61.38,151.8) 61.16,152.02 U51.26
  TOP w0.508: v1(72.43,150.41) C205.2 ; v1(43.73,149.39) FB8.1 ; C203.2 v1(65.32,159.93) ; C223.2 v1(55.24,150.41) ; v1(72.43,152.95) C222.2 ; C215.2 v1(58.97,160.06) ; v1(72.43,154.22) C221.2 ; J26.1 v1(32.41,163.63) ; v1(72.43,151.68) C208.2 ; v1(72.43,149.14) C212.2 ; v1(72.43,146.6) C210.2 ; C224.2 v1(55.24,151.68) ; C213.2 v1(61.51,159.93) ; C207.2 v1(67.22,158.57) ; v1(72.43,155.49) C206.2 ; J27.1 v1(43.84,163.63)
  BOTTOM w0.508: C202.2 60.87,149.26 v1(61.38,149.77) ; C204.2 v1(61.38,150.79) ; C214.2 63.28,151.93 v1(63.41,151.8) ; C201.2 61,148.12 v1(61.38,147.74) ; C216.2 61.63,152.06 v1(61.38,151.8) ; C199.2 C223.2 v1(55.24,150.41)
  vias: v1(61.38,148.75) v1(62.39,150.79) v1(62.39,149.77) v1(62.39,148.75) v1(62.39,147.74) v1(63.41,150.79) v1(63.41,149.77) v1(63.41,148.75) v1(63.41,147.74) v1(64.43,151.8) v1(64.43,150.79) v1(64.43,149.77) v1(64.43,148.75) v1(64.43,147.74) v1(65.44,150.79) v1(65.44,149.77) v1(65.44,148.75) v1(65.44,147.74)
DGND: length 639.2
  TOP w0.254: U9.13 65.17,94.26 v1(65.44,94.53) ; U7.28 v1(84.14,104.49) ; U2.34 v1(115.75,89.06) ; U7.39 v1(88.54,101.76) ; U7.21 v1(84.14,107.42) ; U4.10 v1(117.75,107.5) ; U6.10 v1(88.54,97.51) ; U23.2 v1(92.5,141.91) ; U7.45 v1(90.94,101.76) ; U6.39 v1(88.54,89) ; v1(117.66,91.68) 117.75,91.59 U2.39 ; U7.4 v1(90.94,110.07) ; U9.12 v1(65.31,93.76) ; U4.28 v1(113.35,104.53) ; U6.4 v1(90.94,97.37) ; U6.15 v1(86.54,94.86) ; U4.21 v1(113.35,107.51) ; U9.10 v1(65.44,92.76) ; U6.34 v1(86.54,91.65) ; v1(119.87,91.99) 120.15,91.71 U2.45 ; U2.15 v1(115.75,94.8) ; U23.11 v1(96.04,145.44) ; U4.34 v1(115.75,104.42) ; U7.34 v1(86.54,104.35) ; v1(113.19,88.94) 113.35,89.09 U2.28 ; U4.39 v1(117.75,104.42) ; U2.21 113.35,95.1 v1(113.04,94.79) ; U4.4 v1(120.15,107.51) ; U2.4 v1(120.15,97.45) ; U7.15 v1(86.54,107.56) ; U4.15 115.75,107.61 v1(115.63,107.5) ; U6.21 v1(84.14,94.72) ; U4.45 v1(120.15,104.4) ; U6.45 v1(90.94,89.14) ; U7.10 v1(88.54,110.21) ; U6.28 v1(84.14,91.86) ; U2.10 v1(117.75,94.8)
  TOP w0.279: U51.42 63.16,145.45 v1(63.54,145.07) 63.66,145.19 U51.43
  TOP w0.305: U10.2 60.67,83.93 ; v1(60.62,79.54) 60.8,79.36 U11.2
  TOP w0.381: C217.2 v1(63.68,144.04) ; R30.1 v1(69.13,78.65) ; Q10.S v1(164.74,20.09) ; C219.2 v1(57.57,144.96) ; R152.1 v1(72.34,62.52) ; v1(44.93,146.28) FB8.2 ; U9.16 62.91,93.63 v1(63.16,93.38) ; Y2.2 v1(74.78,64.22) ; 64.05,106.46 v1(64.05,107.23) ; 31.66,125.51 v1(32.42,125.51) ; C156.2 v1(114.46,75.48) ; C151.2 v1(105.32,84.62) ; C230.2 v1(105.32,151.04) ; U9.5 62.16,91.33 v1(62.27,91.22) ; C76.2 v1(149.01,79.41) ; Q18.S v1(16.75,103.47) ; J12.5 v1(165.31,60.51) ; SW10.4 v1(17.79,14.86) ; C53.2 14.64,141.26 v1(14.39,141.52) ; Q7.S v1(11.92,19.26) ; R141.1 v1(30.9,101) ; R149.1 v1(57.06,54.52) ; C5.2 v1(125.13,138.77) ; C49.2 146.81,160.14 v1(147.23,160.57) U14.1 ; R118.1 v1(9.56,16.55) ; R146.1 v1(86.91,28.36) ; 31.66,95.03 v1(32.42,95.03) ; C46.2 v1(61.63,100.37) ; v1(74.71,76.23) Y5.2 ; R123.1 v1(17.82,32.8) ; Q6.S v1(16.37,19.26) ; 62.78,106.46 v1(62.78,107.23) ; C128.2 v1(67.86,24.68) ; C134.2 v1(73.06,39.41) ; C166.2 v1(103.43,54.16) ; R151.1 v1(57.06,49.44) ; Q2.S v1(34.28,19.26) ; Q3.S v1(29.7,19.26) ; C78.2 v1(87.03,151.29) ; C40.2 60.36,84.24 v1(60.49,84.11) 60.67,83.93 ; Q8.S v1(6.82,19.26) ; R244.1 v1(111.54,152.18) ; Q15.S v1(16.75,118.73) ; C8.2 v1(36.11,88.81) ; R122.1 v1(38.52,32.8) ; R159.1 v1(40.55,76.75) ; C133.2 v1(72.3,36.74) ; v1(54.39,86.27) U1.4 ; U16.4 v1(146.21,136.44) ; Q17.S v1(16.75,108.57) ; U40.8 v1(58.07,29.38) ; U13.4 v1(65,98.78) ; SW7.3 v1(45.95,7.2) ; J14.5 v1(165.16,91.63) ; SW10.3 v1(17.79,5.34) ; C123.2 v1(52.74,44.87) ; v1(47.79,89.57) 48.03,89.33 U12.2 ; R143.1 v1(20.99,106.08) ; R113.1 v1(18.45,16.55) ; C74.2 v1(152.18,88.81) ; Q5.S v1(20.79,19.26) ; C56.2 v1(11.72,131.86) ; 51.98,39.15 v1(52.74,39.15) ; C131.2 v1(72.3,34.2) ; C4.2 v1(95.92,122.72) ; SW7.4 v1(45.09,14.68) ; R150.1 v1(57.06,51.98) ; U5.36 v1(73.82,106.59) ; R240.1 v1(130.21,151.68) ; C229.2 v1(111.16,149.77) ; R144.1 v1(21.12,101) ; C58.2 v1(142.79,137.71) ; C143.2 v1(109.64,73.44) ; R140.1 v1(30.9,106.08) ; R10.1 v1(38.52,94.4) ; C79.2 91.96,150.8 v1(91.96,151.29) ; Q1.S v1(36.66,19.26) ; SW9.4 v1(27.95,14.86) ; Q14.S v1(28.18,103.47) ; J22.10 v1(53,66.59) ; Q11.S v1(28.18,118.71) ; R139.1 v1(30.9,111.16) ; C142.2 v1(114.46,72.3) ; U42.2 60.87,24.68 v1(60.49,24.29) 60.76,24.02 U42.3 ; C157.2 v1(82.97,62.78) ; R137.1 v1(30.9,116.24) ; Q16.S v1(16.75,113.65) ; U5.13 v1(73.82,87.5) ; C122.2 v1(52.74,28.99) ; C132.2 v1(72.3,32.3) ; R115.1 v1(27.34,16.55) ; Q13.S v1(28.18,108.55) ; Q9.S v1(22.66,120.19) ; Q4.S v1(25.23,19.26) ; C124.2 v1(51.22,33.69) ; C136.2 v1(68.36,64.81) ; C126.2 v1(38.52,29.25) ; U5.48 v1(67.82,109.17) ; v1(68.24,76.62) R229.1 ; U13.5 v1(65,102.98) ; C68.2 v1(148.88,48.3) ; C51.2 v1(150.28,145.83) ; SW9.3 v1(27.95,5.4) ; C43.2 v1(69.13,79.92) ; C227.2 v1(123.1,150.91) ; v1(54.39,83.73) U1.2 ; C129.2 v1(160.57,15.15) ; U27.4 v1(83.69,155.53) ; R138.1 v1(20.99,116.24) ; C39.2 v1(69.13,84.37) ; U39.8 v1(58.07,39.54) ; R117.1 v1(14.01,16.55) ; U19.15 v1(158.79,54.52) 158.91,54.65 C60.2 ; C127.2 v1(17.82,29.25) ; R116.1 v1(22.9,16.55) ; C10.2 v1(38.52,88.05) ; R119.1 v1(4.48,16.55) ; v1(54.39,85) U1.3 ; C226.2 v1(129.2,149.77) ; C137.2 v1(56.68,73.44) ; C57.2 v1(145.33,142.79) ; C70.2 v1(156.39,88.3) ; C145.2 v1(109.64,69.25) ; R114.1 v1(31.79,16.55) ; C59.2 v1(156.39,57.19) ; 39.28,125.51 v1(40.17,125.51) ; R148.1 v1(57.06,57.06) ; C9.2 v1(31.03,88.81) ; J22.2 v1(50.39,77.89) ; v1(97.57,129.83) C7.2 ; C135.2 v1(95.03,119.93) ; R121.1 v1(28.61,32.8) ; R26.1 v1(69.13,83.1) ; R112.1 v1(36.23,16.55) ; C69.2 158.91,85.76 v1(158.79,85.64) 157.25,85.64 ; C11.2 v1(41.06,88.05) ; R124.1 v1(18.33,122.59) ; U26.5 v1(91.73,154.85) ; R128.1 v1(163.23,14.9) ; R13.1 v1(34.07,73.7) ; U25.5 v1(96.18,154.85) ; C63.2 v1(152.31,57.7) ; R142.1 v1(20.99,111.16) ; v1(55.66,83.22) C1.2 ; C130.2 v1(37.76,5.75) ; Q12.S v1(28.18,113.65) ; C125.2 v1(28.61,29.25) ; U5.25 v1(79.32,106.93)
  TOP w0.508: v2(96.34,67.13) U43.L8 ; v2(100.34,66.13) U43.M11 ; v2(100.34,68.13) U43.K11 ; v2(96.34,72.13) U43.G8 ; v2(96.34,71.13) U43.H8 ; v2(90.33,77.13) U43.B2 ; v2(96.34,70.13) U43.J8 ; v2(99.34,67.13) U43.L10 ; v2(107.34,78.13) U43.A18 ; v2(95.34,71.13) U43.H7 ; v2(97.34,67.13) U43.L9 ; v2(100.34,67.13) U43.L11 ; v2(98.15,95.97) U3.H7 ; v2(106.34,77.13) U43.B17 ; v2(90.33,61.12) U43.U2 ; v2(107.34,60.13) U43.V18 ; v2(98.15,101.97) U3.H2 ; v2(97.34,68.13) U43.K9 ; v2(89.34,60.13) U43.V1 ; v2(89.34,78.13) U43.A1 ; v2(100.34,71.13) U43.H11 ; v2(101.34,67.13) U43.L12 ; v2(97.34,71.13) U43.H9 ; v2(106.34,61.12) U43.U17 ; v2(101.15,94.97) U3.E8 ; v2(99.34,70.13) U43.J10 ; U8.4 v1(70.9,69.13) ; v2(99.34,71.13) U43.H10
  TOP w0.61: C47.2 20.99,138.21 v1(20.87,138.09) U15.15
  TOP w0.635: U52.6 v1(121.98,161.81) ; U52.6 v1(124.37,163.11) ; U52.6 v1(126.88,161.81) ; U53.6 v1(106.59,162.98) ; U53.6 v1(104.08,161.81) ; U53.6 v1(108.98,161.81) ; U53.3 v1(106.59,154.22) v1(106.59,153.33) ; J6.20 J6.19 ; v1(124.62,153.58) 124.37,153.83 v1(124.37,154.34) U52.3 ; C12.2 v1(122.34,65.19) ; 106.46,123.74 v1(106.46,122.97)
  TOP w0.762: C48.2 v1(22.14,141.9)
  LY2_GND w0.483: 31.99,75.09 J5.20 32.8,74.48 ; 34.89,75.09 J5.19 34.07,74.48 ; 37.25,74.48 J6.20 36.44,75.09 ; 39.33,75.09 J6.19 38.52,74.48
  LY2_GND w0.635: 120.18,58.58 119.16,58.58
  LY2_GND w0.762: J4.3 85,126.55 ; J4.3 85.91,125.64 ; J4.3 84.09,125.64 ; J4.3 85,124.73 ; 40.91,116.75 J2.7 ; J2.7 41.82,117.66 ; J2.7 41.82,115.84 ; J2.7 42.73,116.75 ; 88.53,38.52 J20.19 87.92,39.33 ; J3.37 119.29,137.98 ; J3.37 118.38,137.07 ; J3.37 119.29,136.16 ; J3.37 120.2,137.07 ; 152.45,18.33 U41.M1 ; U41.M1 153.98,16.8 ; U41.M1 155.5,18.33 ; U41.M1 153.98,19.85 ; 146.28,16.8 U41.M2 ; U41.M2 147.8,18.33 ; U41.M2 144.75,18.33 ; U41.M2 146.28,19.85 ; J2.8 44.36,117.66 ; J2.8 43.45,116.75 ; J2.8 45.27,116.75 ; J2.8 44.36,115.84 ; TP41.1 166.69,12.61 ; TP41.1 165.65,13.65 ; TP41.1 165.65,11.57 ; TP41.1 164.6,12.61 ; 42.81,31.03 J18.9 ; J18.9 43.73,30.11 ; J18.9 44.64,31.03 ; J18.9 43.73,31.94 ; 73.57,136.16 J3.1 ; J3.1 74.48,137.07 ; J3.1 72.66,137.07 ; J3.1 73.57,137.98 ; 86.27,136.16 J3.11 ; J3.11 85.36,137.07 ; J3.11 87.18,137.07 ; J3.11 86.27,137.98 ; 164.48,98.59 167.17,98.59 ; 167.17,98.59 167.17,101.28 ; 167.17,98.59 167.17,95.9 ; J10.11 8.99,128.36 ; J10.11 6.3,125.67 ; J10.11 8.99,122.97 ; J10.11 11.68,125.67 ; J18.10 46.27,31.94 ; J18.10 47.18,31.03 ; J18.10 45.35,31.03 ; J18.10 46.27,30.11 ; J1.28 37.65,91.35 ; J1.28 36.74,90.44 ; J1.28 35.83,91.35 ; J1.28 36.74,92.26 ; J3.20 96.43,140.52 ; J3.20 96.43,138.7 ; J3.20 97.34,139.61 ; J3.20 95.52,139.61 ; TP38.1 32.93,6.03 ; TP38.1 31.89,4.99 ; TP38.1 32.93,3.95 ; TP38.1 33.97,4.99 ; 108.22,139.61 J3.30 ; J3.30 109.13,140.52 ; J3.30 109.13,138.7 ; J3.30 110.04,139.61 ; 88.53,34.07 J19.19 87.92,34.89 ; J4.20 105.32,129.09 ; J4.20 104.41,128.18 ; J4.20 106.23,128.18 ; J4.20 105.32,127.27 ; 33.29,91.35 J1.27 ; J1.27 34.2,92.26 ; J1.27 34.2,90.44 ; J1.27 35.11,91.35 ; 164.48,67.47 167.17,67.47 ; 167.17,67.47 167.17,64.78 ; 167.17,67.47 167.17,70.17 ; 164.48,73.6 167.17,73.6 ; 167.17,73.6 167.17,76.29 ; 167.17,73.6 167.17,70.9 ; 123.33,165.01 TP40.1 ; TP40.1 124.37,166.05 ; TP40.1 124.37,163.97 ; TP40.1 125.41,165.01 ; J3.10 84.64,139.61 ; J3.10 83.73,140.52 ; J3.10 83.73,138.7 ; J3.10 82.82,139.61 ; 88.53,37.25 J20.20 87.92,36.44 ; 8.99,97.98 J10.10 ; J10.10 6.3,100.67 ; J10.10 11.68,100.67 ; J10.10 8.99,103.36 ; 87.92,31.99 J19.20 88.53,32.8 ; 112.03,125.64 J4.25 ; J4.25 112.94,126.55 ; J4.25 112.94,124.73 ; J4.25 113.85,125.64 ; 167.17,39.79 167.17,42.48 ; 167.17,42.48 164.48,42.48 ; 167.17,42.48 167.17,45.17 ; 96.79,128.18 J4.14 ; J4.14 97.7,127.27 ; J4.14 97.7,129.09 ; J4.14 98.61,128.18 ; J10.5 10.41,108.58 ; J10.5 11.37,107.63 ; J10.5 9.46,107.63 ; J10.5 10.41,106.68 ; 2.68,149.14 TP39.1 ; TP39.1 3.72,148.09 ; TP39.1 3.72,150.18 ; TP39.1 4.76,149.14
  LY7_GND w0.483: 34.07,74.48 J5.19 34.89,75.09 ; 36.44,75.09 J6.20 37.25,74.48 ; 31.99,75.09 J5.20 32.8,74.48 ; 39.33,75.09 J6.19 38.52,74.48
  LY7_GND w0.762: 144.75,18.33 U41.M2 ; U41.M2 147.8,18.33 ; U41.M2 146.28,19.85 ; U41.M2 146.28,16.8 ; 112.94,124.73 J4.25 ; J4.25 112.94,126.55 ; J4.25 112.03,125.64 ; J4.25 113.85,125.64 ; 3.72,148.09 TP39.1 ; TP39.1 4.76,149.14 ; TP39.1 2.68,149.14 ; TP39.1 3.72,150.18 ; J3.1 73.57,137.98 ; J3.1 72.66,137.07 ; J3.1 74.48,137.07 ; J3.1 73.57,136.16 ; J10.10 8.99,103.36 ; J10.10 11.68,100.67 ; J10.10 8.99,97.98 ; J10.10 6.3,100.67 ; J2.7 42.73,116.75 ; J2.7 41.82,117.66 ; J2.7 40.91,116.75 ; J2.7 41.82,115.84 ; 46.27,30.11 J18.10 ; J18.10 47.18,31.03 ; J18.10 46.27,31.94 ; J18.10 45.35,31.03 ; J18.9 44.64,31.03 ; J18.9 43.73,31.94 ; J18.9 42.81,31.03 ; J18.9 43.73,30.11 ; 85.36,137.07 J3.11 ; J3.11 87.18,137.07 ; J3.11 86.27,136.16 ; J3.11 86.27,137.98 ; 167.17,67.47 167.17,70.17 ; 167.17,67.47 167.17,64.78 ; 167.17,67.47 164.48,67.47 ; TP40.1 125.41,165.01 ; TP40.1 124.37,166.05 ; TP40.1 123.33,165.01 ; TP40.1 124.37,163.97 ; TP41.1 166.69,12.61 ; TP41.1 165.65,13.65 ; TP41.1 165.65,11.57 ; TP41.1 164.6,12.61 ; J2.8 44.36,117.66 ; J2.8 44.36,115.84 ; J2.8 43.45,116.75 ; J2.8 45.27,116.75 ; 164.48,73.6 167.17,73.6 ; 167.17,73.6 167.17,70.9 ; 167.17,73.6 167.17,76.29 ; 97.7,127.27 J4.14 ; J4.14 96.79,128.18 ; J4.14 98.61,128.18 ; J4.14 97.7,129.09 ; TP38.1 32.93,6.03 ; TP38.1 31.89,4.99 ; TP38.1 33.97,4.99 ; TP38.1 32.93,3.95 ; 88.53,37.25 J20.20 87.92,36.44 ; 88.53,32.8 J19.20 87.92,31.99 ; 119.29,136.16 J3.37 ; J3.37 120.2,137.07 ; J3.37 118.38,137.07 ; J3.37 119.29,137.98 ; J1.27 34.2,92.26 ; J1.27 34.2,90.44 ; J1.27 33.29,91.35 ; J1.27 35.11,91.35 ; J3.20 96.43,140.52 ; J3.20 95.52,139.61 ; J3.20 97.34,139.61 ; J3.20 96.43,138.7 ; U41.M1 155.5,18.33 ; U41.M1 153.98,16.8 ; U41.M1 152.45,18.33 ; U41.M1 153.98,19.85 ; 85,124.73 J4.3 ; J4.3 85,126.55 ; J4.3 85.91,125.64 ; J4.3 84.09,125.64 ; 36.74,90.44 J1.28 ; J1.28 35.83,91.35 ; J1.28 36.74,92.26 ; J1.28 37.65,91.35 ; J3.10 84.64,139.61 ; J3.10 83.73,138.7 ; J3.10 83.73,140.52 ; J3.10 82.82,139.61 ; 104.41,128.18 J4.20 ; J4.20 106.23,128.18 ; J4.20 105.32,129.09 ; J4.20 105.32,127.27 ; 88.53,34.07 J19.19 87.92,34.89 ; 167.17,95.9 167.17,98.59 ; 167.17,98.59 167.17,101.28 ; 167.17,98.59 164.48,98.59 ; 108.22,139.61 J3.30 ; J3.30 109.13,140.52 ; J3.30 109.13,138.7 ; J3.30 110.04,139.61 ; 87.92,39.33 J20.19 88.53,38.52 ; J10.11 8.99,128.36 ; J10.11 11.68,125.67 ; J10.11 8.99,122.97 ; J10.11 6.3,125.67 ; 9.46,107.63 J10.5 ; J10.5 11.37,107.63 ; J10.5 10.41,106.68 ; J10.5 10.41,108.58 ; 164.48,42.48 167.17,42.48 ; 167.17,42.48 167.17,39.79 ; 167.17,42.48 167.17,45.17
  BOTTOM w0.381: C81.2 93.13,145.58 v1(93.26,145.45) ; J15.28 v1(104.23,165.08) ; v1(60.62,79.54) 60.87,79.79 C44.2 ; C154.2 109.77,70.4 v1(110.4,69.76) ; C29.2 118.24,107.99 v1(117.75,107.5) ; v1(113.35,104.53) 113.96,103.92 C26.2 ; v1(74.71,106.68) 74.71,107.03 74.84,107.16 C23.2 ; v1(84.14,104.49) 84.71,103.92 C35.2 ; C17.2 v1(97.79,102.78) ; J15.6 v1(84.45,151.26) ; v1(113.04,94.79) 113.08,94.79 C15.2 ; v1(120.15,97.45) 119.64,96.94 C16.2 ; C150.2 C148.2 104.69,83.98 v1(105.32,84.62) ; J15.3 v1(91.96,151.29) ; C145.2 v1(109.64,69.25) ; v1(74.71,87.5) 74.71,87.86 74.4,88.18 C22.2 ; v1(90.94,110.07) 90.51,109.64 C38.2 ; v1(117.75,104.42) 118.24,103.92 C28.2 ; v1(103.29,55.92) C163.2 C162.2 ; v1(84.14,107.42) 84.37,107.64 84.37,107.8 85,108.43 C37.2 ; C80.2 92.75,142.15 v1(92.5,141.91) ; v1(73.82,106.59) 73.7,106.72 73.57,106.72 C25.2 C24.2 ; C42.2 v1(63.16,93.38) 63.28,93.51 64.55,93.51 C41.2 ; v1(74.71,90.17) 74.71,89.76 74.4,89.45 C21.2 ; J15.18 v1(85.31,151.24) ; R259.1 v1(99.22,91.45) ; C149.2 91.99,83.1 92.37,83.49 v1(92.75,83.49) ; J15.21 v1(91.1,151.29) ; 91.35,145.83 v1(91.35,146.6) ; C45.2 v1(47.79,89.57) ; C159.2 v1(87.67,69.89) ; v1(104.43,119.13) J21.10 ; R27.1 v1(62.27,91.22) ; C153.2 v1(109.64,62.01) ; C27.2 113.83,107.99 v1(113.35,107.51) ; v1(52.74,39.15) 53.25,38.65 R103.1 ; v1(119.87,91.99) 119.87,91.93 119.29,91.35 C14.2 ; C164.2 v1(92.62,55.16) ; J15.27 v1(75.93,164.94) ; C158.2 v1(86.27,75.48) ; v1(113.19,88.94) 114.21,89.95 C13.2 ; C161.2 v1(87.03,61.38) ; C152.2 v1(109.64,76.24) ; v1(88.54,101.76) 89.45,102.67 C36.2 ; v1(90.72,83.01) C147.2 ; C19.2 v1(97.7,98.97) ; v1(109.64,71.54) 109.64,72.24 C146.2 ; C220.2 v1(58.84,145.96) ; R17.1 v1(109.13,99.61) ; C165.2 v1(91.35,55.16)
  BOTTOM w0.508: v2(101.15,94.97) 101.64,94.48 C20.2 ; 72.94,72.94 v1(72.17,72.94) ; v2(97.34,71.13) 97.75,71.54 C138.2 ; v2(99.34,67.13) 98.92,66.71 C139.2 ; v2(97.34,68.13) 97.72,68.13 98.21,68.62 C140.2 ; v1(63.54,145.07) 64.3,145.83 C218.2 ; v2(96.34,70.13) 96.3,70.09 C160.2 ; v2(100.34,68.13) 101,68.79 C155.2 ; v2(99.34,70.13) 99.1,69.89 99.1,69.13
  BOTTOM w0.635: C32.2 84.14,95.06 v1(84.14,94.72) ; C18.2 v1(94.91,99.48) ; C33.2 89.12,96.94 v1(88.54,97.51) ; v1(84.14,91.86) 84.14,91.79 84.71,91.22 C30.2 ; C31.2 89.19,90.21 88.56,89.57 88.56,89.01 v1(88.54,89)
  vias: v1(12.4,128.48) v1(13.25,124.11) v1(14.13,127.16) v1(23.02,114.85) v1(23.15,113.96) v1(30.45,91.67) v1(92.49,145.45) v1(92.49,144.69) v1(92.49,143.93) v1(93.26,144.69) v1(93.26,143.93) v1(94.02,145.45) v1(94.02,144.69) v1(94.02,143.93)
GND_CAN0: length 75.3
  TOP w0.508: J11.3 v1(165.54,143.33) ; v1(150.15,152.95) U14.4 ; v1(165.62,148.86) J11.5 ; v1(157.01,136.44) U16.5 ; v1(150.15,150.41) U14.5 ; v1(162.34,140.25) U17.3 ; v1(165.71,139.17) J11.6 ; v1(160.91,144.48) C54.2 ; v1(152.31,146.6) C52.2
  BOTTOM w0.508: v1(162.34,140.25) 163.36,140.25 164.43,139.17 v1(165.71,139.17) 165.71,143.16 v1(165.54,143.33) 165.54,143.56 164.63,144.48 ; v1(162.34,140.25) 160.82,140.25 v1(157.01,136.44) ; v1(162.34,140.25) 162.34,135.65 167.17,130.83 ; 164.63,144.48 v1(160.91,144.48) 154.43,144.48 v1(152.31,146.6) 152.31,148.25 v1(150.15,150.41) v1(150.15,152.95) ; 164.63,144.48 164.63,147.87 v1(165.62,148.86) 164.84,149.64 164.84,153.49 167.17,155.82
GNDA_TSC: length 862.9
  TOP w0.095: 107.61,119.42 107.61,121.96 107.99,122.34 108.5,122.34 108.88,121.96 108.88,119.54 109.13,119.29 ; 122.21,54.14 119.33,54.14
  TOP w0.121: 120.18,57.31 119.28,57.31 119.03,57.56 119.03,64.68 124.88,70.52 124.88,112.57 121.96,115.49 111.6,115.49 109.89,117.2 109.89,118.53 109.13,119.29 ; J9.3 6.51,143.42 6.13,143.8 6.13,145.07 7.02,145.96 22.64,145.96 32.04,136.56 32.04,134.66 31.91,134.53 31.66,134.53 31.28,134.16 31.28,132.99 31.16,132.87 30.81,132.87 29.39,131.46 29.39,123.87 32.95,120.31 33.18,120.31 33.18,120.31 44.87,120.31 45.65,119.52 45.65,119.33 55.65,109.34 63.93,109.34 67.6,113.01 103.55,113.01 107.54,116.99 107.54,118.64 107.82,118.92 108.74,118.92 109.31,118.34 109.31,117.07 111.39,114.99 121.75,114.99 124.38,112.36 124.38,70.76 118.54,64.91 118.54,54.93 119.33,54.14 ; J8.5 34.71,131.36 34.07,131.99 31.53,131.99 31.28,132.24 31.28,132.26 31.16,132.38 31.01,132.38 29.89,131.25 29.89,124.11 33.18,120.81 45,120.81 45,120.81 45.1,120.81 46.15,119.76 46.15,119.54 55.85,109.83 63.72,109.83 67.39,113.5 103.35,113.5 107.04,117.19 107.04,118.84 ; J9.5 5.24,143.42 5.5,143.67 5.5,145.2 6.77,146.47 23.15,146.47 32.8,136.82 32.8,134.91 33.82,133.9 33.82,133.51 34.07,133.26 38.14,133.26 38.52,132.88 v1(38.52,131.36) ; 122.21,54.14 122.47,54.39 122.47,57.06 122.21,57.31 J7.11 ; 107.04,118.84 107.04,118.85 107.61,119.42 ; 107.04,118.84 107.04,118.84 106.84,119.04 105.96,119.04 105.7,119.29 J21.12
  TOP w0.508: J8.12 38.52,127.55 ; 38.52,127.55 J8.11 ; 38.52,127.55 v1(38.52,131.36) ; v1(38.52,131.36) J8.6 ; v1(38.52,131.36) J8.5 ; J9.5 J9.4 J9.2 J9.3 ; 120.18,57.31 J7.11 ; 105.7,121.45 J21.12
  LY3 w0.121: J21.12 107.1,118.78 107.1,118.53 108.62,117 114.84,117 122.97,108.87 122.97,57.82 122.47,57.31 J7.11 ; 105.7,121.45 105.7,123.61 106.34,124.24 106.34,130.21 v1(105.96,130.59) 106.34,130.97 106.34,132.63 105.64,133.32 105.64,133.82 105.97,134.15 v1(107.23,134.15) 109.38,131.99 109.38,131.98 109.44,131.92 109.44,131.68 109.76,131.36 110.52,131.36 110.84,131.03 110.84,130.41 111.84,129.4 111.84,124.42 111.04,123.61 111.04,122.31 111.43,121.92 111.43,121.19 111.8,120.81 111.8,119.29 112.1,118.99 115.66,118.99 116.17,118.48 125.01,109.64 125.01,54.52 122.07,51.59 119.55,51.59 119.16,51.98 119.16,56.3 120.18,57.31
  BOTTOM w0.121: 60.62,134.28 71.8,134.28 72.82,133.26 105.07,133.26 105.96,134.15 v1(107.23,134.15) 109.44,131.93 109.44,131.55 109.64,131.36 110.52,131.36 110.84,131.03 110.84,130.66 110.26,130.09 109.26,130.09 108.75,130.59 v1(105.96,130.59) 105.32,131.23 72.05,131.23 72,131.28 71.03,132.24 61.41,132.24 60.82,131.65 60.56,131.4 57.78,131.4 56.34,131.4 56.09,131.65 55.8,131.94 55.57,132.17 51.9,132.17 48,128.27 47.07,128.27 46.39,128.94 31.78,128.94 31.21,128.37 30.84,128.37 30.58,128.63 30.58,130.27 30.84,130.53 36.93,130.53 38.2,131.8 38.2,135.98 38.46,136.24 38.83,136.24 39.52,135.55 47.66,135.55 49.06,134.15 56.43,134.15 57.19,133.39 59.73,133.39 60.62,134.28
V1_8D: length 35.3
  TOP w0.279: U51.36 v1(58.97,147.02)
  TOP w0.381: U40.16 v1(53.52,34.98)
  TOP w0.635: v1(107.35,148.37) v1(106.59,148.37) R241.1 v1(105.83,149.26) ; v1(60.36,67.86) 60.87,67.35 R6.1
  TOP w0.762: R166.2 v1(113.2,80.31) ; v1(74.08,35.85) C133.1 75.98,36.74 J20.2 ; R168.2 v1(106.59,53) ; v1(60.36,71.79) 60.87,72.3 R9.1 v1(59.59,73.31) ; R162.2 v1(83.1,64.68) ; C10.1 v1(36.87,88.18) ; R8.1 v1(125.13,143.42) ; C124.1 v1(52.74,34.71) ; R126.2 v1(67.09,26.96) ; C3.1 34.07,124.5 J1.1 ; R6.1 v1(59.61,66.21) ; v1(125.64,98.34) R7.1 v1(126.65,97.2) ; R164.2 v1(107.23,84.37) ; C219.1 v1(56.43,147.99)
  LY3 w0.762: v1(36.87,88.18) 36.87,86.91 J6.2
  LY5_PWR w0.483: 36.44,86.52 J6.2 37.25,87.13
  LY5_PWR w1.143: 76.49,36.44 J20.2 75.88,37.25 ; 34.2,125.28 J1.1 33.29,124.37
  BOTTOM w0.762: v1(58.97,147.02) 59.01,146.98 C220.1
V3_3AUD: length 11.7
  TOP w0.279: U51.17 64.16,153.95 v1(64.43,154.22) 64.66,153.98 U51.16 ; v1(58.97,152.44) 59.05,152.52 U51.25 ; U51.24 60.32,153.25 60.11,153.45 v1(60.11,153.83)
  TOP w0.508: C203.1 v1(65.32,155.87) ; C215.1 v1(58.97,155.87) ; FB9.2 v1(63.41,155.87) ; C213.1 v1(61.51,155.87)
  BOTTOM w0.508: v1(58.97,152.44) 59.6,151.8 C204.1 ; v1(64.43,154.22) 64.3,154.09 C214.1 ; C216.1 60.62,153.33 v1(60.11,153.83)
V3_3D: length 131.2
  TOP w0.254: U2.18 v1(114.55,97.7) ; U4.7 118.95,110.11 v1(118.91,110.15) ; U6.18 v1(85.34,97.57) ; U6.7 v1(89.74,94.86) ; U2.7 v1(118.95,94.78) ; U4.18 v1(114.55,110.11)
  TOP w0.279: v1(65.7,145.07) 65.16,145.61 U51.46 ; U51.45 64.66,145.18 v1(64.55,145.07) 64.16,145.46 U51.44
  TOP w0.356: U9.1 61.9,94.26 61.63,94.53 v1(61.25,94.53) ; v1(64.68,95.16) 64.43,95.16 63.91,94.64 U9.14 ; U9.15 v1(63.41,95.16)
  TOP w0.381: U40.1 v1(53.52,27.07) ; 44.23,51.98 v1(44.36,51.98) ; C121.1 v1(52.74,38.14) ; C123.1 v1(52.74,43.85) ; U27.1 v1(81.36,154.18) ; C70.1 v1(158.39,88.32) ; U39.1 v1(53.52,37.23) ; C60.1 158.91,55.66 v1(158.79,55.79) U19.16 ; C59.1 v1(158.39,57.08) ; U42.5 v1(65.14,24.68) ; U10.7 66.28,83.93 v1(66.46,84.11) ; C69.1 158.91,86.78 v1(158.79,86.91) 157.25,86.91 ; C122.1 v1(52.74,27.98) ; U39.16 v1(53.52,45.14) ; U11.7 66.4,79.36 v1(66.59,79.54)
  TOP w0.406: U13.8 v1(61.69,102.98)
  TOP w0.508: v1(100.15,102.97) U3.F1 ; v2(99.15,97.97) U3.G5 ; 76.55,72.94 v1(74.97,72.94) ; v2(103.15,94.97) U3.D8
  TOP w0.61: C47.1 20.99,139.23 v1(20.87,139.36) U15.16
  TOP w0.635: v1(122.21,149.26) R237.1 v1(124.37,148.5) v1(125.01,147.87) ; R2.1 62.78,67.22 63.41,67.86 v1(64.17,67.86) ; C12.1 v1(121.32,65.19)
  TOP w0.762: SW8.8 v1(44.36,49.44) ; SW8.5 v1(44.36,57.06) ; R163.2 v1(109.13,84.37) ; R165.2 v1(114.34,77.38) ; v1(62.78,72.17) R5.1 63.55,73.31 64.05,72.81 v1(64.05,72.3) ; v1(66.59,79.54) 66.97,79.92 C43.1 ; C5.1 v1(125.13,137.76) ; R3.1 v1(125.64,100.24) ; R235.2 v1(22.14,11.34) ; R2.1 v1(63.91,66.21) ; v1(61.63,101.38) 61.63,101.38 C46.1 ; U12.1 v1(47.8,90.83) ; Y5.4 v1(71.05,79.9) ; R236.2 v1(11.98,11.34) ; v1(66.46,84.11) 66.71,84.37 C39.1 ; J21.2 99.1,119.93 v1(97.71,119.93) C135.1 ; SW8.6 v1(44.36,54.52) ; C48.1 18.98,141.77 v1(17.69,141.77) ; C217.1 v1(65.68,144.06) ; R24.2 R23.2 v1(64.17,86.52) ; R57.2 v1(78.65,151.29) ; SW8.7 44.23,51.98 ; R31.2 v1(65.19,97.19) ; FB9.1 v1(63.41,159.9) ; C136.1 v1(69.13,66.59) ; Y2.4 v1(71.03,67.6) ; C128.1 v1(65.14,24.68) ; R4.1 v1(125.01,145.33) ; U16.1 v1(147.8,144.88) ; R127.2 v1(37.76,9.31) ; U14.2 v1(147.23,158.03) 146.81,158.45 C49.1 ; C4.1 v1(97.7,121.83) ; C51.1 v1(149.26,145.83) ; R161.2 v1(82.97,66.59) ; R160.2 v1(113.2,68.99) ; R21.2 v1(65.32,70.4) ; R167.2 v1(108.5,53.12)
  LY3 w0.381: v1(121.32,65.19) 120.5,65.19 120.18,64.87 120.18,63.66 ; v1(99.79,124.52) 100.24,124.98 J4.15
  LY4_PWR w0.762: 119.37,63.66 120.18,63.66 120.18,64.27 ; 120.92,137.07 J3.39 ; J3.39 121.83,136.16 ; J3.39 121.83,137.98 ; J3.39 122.74,137.07 ; 98.74,120.18 J21.2 99.35,119.37 ; 99.33,125.64 J4.15 ; J4.15 100.24,126.55 ; J4.15 100.24,124.73 ; J4.15 101.15,125.64
  BOTTOM w0.635: v1(85.34,97.57) 85,97.23 C32.1 ; C33.1 89.49,95.92 89.74,95.67 v1(89.74,94.86) ; C19.1 99.48,98.3 v2(99.15,97.97) ; C18.1 v1(95.03,98.46) ; 99.1,93.89 v1(99.1,93.13)
  BOTTOM w0.762: v1(114.55,97.7) 114.55,97.28 C15.1 ; v1(109.13,98.34) 109.13,98.34 R16.2 ; C29.1 118.66,109.89 v1(118.91,110.15) ; C45.1 48.04,90.59 v1(47.8,90.83) ; v1(61.25,94.53) 61.63,94.53 61.76,94.4 C42.1 ; R22.2 v1(72.17,71.67) ; v1(52.74,27.98) 52.87,27.98 53.38,28.49 ; C41.1 v1(64.68,95.16) ; v1(63.79,92.75) 63.92,92.75 64.17,92.49 R25.2 ; v2(103.15,94.97) 102.65,94.48 C20.1 ; v1(65.7,145.07) 65.32,145.45 65.32,145.96 ; R100.2 54.01,44.64 v1(53.52,45.14) ; v1(118.95,94.78) 118.95,95.58 C16.1 ; v1(114.55,110.11) 114.21,109.77 C27.1 ; R15.2 v1(102.15,103.54) ; C34.1 v1(74.97,72.94) ; C17.1 99.96,102.78 v1(100.15,102.97) ; R101.2 v1(52.87,33.57)
  vias: v1(125.64,99.48)
V5_0D: length 38.3
  TOP w0.381: C9.1 32.8,88.68 v1(33.31,88.18) ; C8.1 v1(34.33,88.05)
  TOP w0.508: J5.1 34.96,87.41 39.66,87.41 40.17,86.91 40.17,82.97 42.33,80.81 R12.2
  TOP w0.762: C2.1 v1(40.17,124.5) ; C132.1 v1(75.21,32.3) 75.98,32.3 J19.2 ; C131.1 v1(75.21,34.2) 76.36,34.2 J19.1 ; R145.2 v1(90.72,34.2)
  LY3 w0.762: v1(34.33,88.05) 34.33,86.78 J5.1 ; v1(33.31,88.18) 33.06,87.92 33.06,86.78 J5.2
  LY4_PWR w0.483: 32.8,87.13 J5.2 31.99,86.52 ; 34.89,86.52 J5.1 34.07,87.13
  LY4_PWR w1.143: J1.2 37.65,124.37 ; J1.2 36.74,123.46 ; J1.2 36.74,125.28 ; 76.49,34.89 J19.1 75.88,34.07 ; 75.88,32.8 J19.2 76.49,31.99
  LY6 w0.762: v1(40.17,124.5) 39.41,124.5 39.28,124.37 J1.2
VDDSHV1: length 46.3
  TOP w0.254: U6.31 v1(85.34,89) ; U6.42 v1(89.74,91.99) ; U7.7 v1(89.74,107.56) ; U7.18 v1(85.34,110.53) ; U7.31 v1(85.34,101.76) ; U7.42 v1(89.74,104.56)
  TOP w0.279: U23.5 v1(94.01,141.9) ; U23.17 v1(92.5,147.47)
  TOP w0.305: U5.39 v1(72.32,106.59) ; U5.34 v1(74.82,109.17) ; v1(73.06,86.91) 73.06,87.54 73.32,87.79 U5.12 v1(73.32,90.21) ; U5.37 v1(73.32,109.17)
  TOP w0.508: U1.8 v1(43.98,82.46) ; R1.2 v1(41.69,84.62) ; R247.2 v1(88.68,142.28) ; v1(50.46,82.46) U1.1 C1.1
  TOP w0.635: R6.2 v1(59.61,64.42) v1(58.59,64.42) ; R2.2 v1(63.91,64.42) v1(64.92,64.42)
  BOTTOM w0.508: v1(73.32,109.17) 73.57,108.92 C25.1 ; C38.1 90.08,107.9 v1(89.74,107.56) ; C24.1 72.3,108.53 72.46,108.69 72.46,109.55 72.2,109.8 v1(72.18,109.8) ; C80.1 93.76,142.14 v1(94.01,141.9) ; C23.1 74.84,109.07 74.82,109.07 v1(74.82,109.17) ; v1(89.74,104.56) 89.45,104.26 C36.1 ; v1(85.34,101.76) 85,102.1 C35.1 ; C37.1 85.34,109.98 v1(85.34,110.53) ; v1(73.32,90.21) 73.06,89.95 C21.1 ; v1(92.5,147.47) 92.11,147.08 C81.1 ; C22.1 v1(73.06,86.91) ; v1(69.76,89.95) R18.2 R20.2 ; R19.2 v1(77.38,89.95)
  BOTTOM w0.635: v1(89.74,91.99) 89.45,91.69 C31.1 ; C30.1 85,89.34 v1(85.34,89)
VDDSHV2: length 12.1
  TOP w0.254: v1(90.46,144.94) U23.21
  TOP w0.508: v1(96.56,129.83) C7.1 ; v1(101.14,148.76) R47.2
  LY3 w0.508: J4.11 96.56,127.04 v1(96.56,129.83)
  LY5_PWR w0.889: 94.25,125.64 J4.11 ; J4.11 95.16,126.55 ; J4.11 96.07,125.64 ; J4.11 95.16,124.73
  BOTTOM w0.508: C77.1 90.59,144.82 v1(90.46,144.94)
VDDSHV3: length 13.5
  TOP w0.254: v1(118.95,101.68) U4.42 ; v1(122.02,108.81) U4.1 121.35,108.09 121.58,107.86 v1(122.08,107.86) ; v1(111.8,107.48) 111.97,107.48 112.15,107.66 U4.24 v1(111.48,108.81) ; v1(114.55,101.68) U4.31
  TOP w0.762: v1(128.44,101.75) R3.2 R7.2
  BOTTOM w0.508: v1(118.95,101.68) 118.66,101.97 C28.1 ; v1(114.55,101.68) 114.21,102.02 C26.1
  vias: v1(128.43,104.05) v1(128.43,103.29) v1(128.43,102.53)
